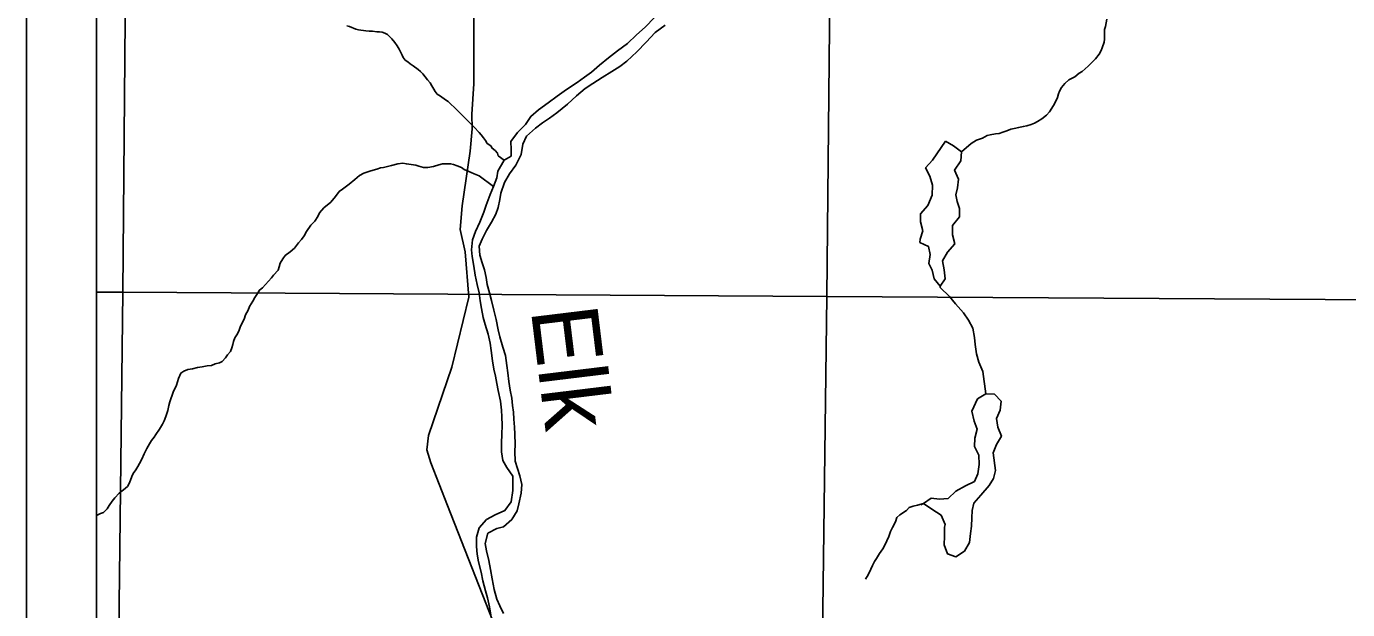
# Model space of a CAD drawing. Extents: x 0 to 34, y 0 to 22.
# Drawn here: x 2 to 3.881, y 17.696 to 18.526 of the extents above; entities that cross this region are included whole.
import ezdxf

# ---------------------------------------------------------------- set-up
doc = ezdxf.new("R2010")
doc.units = 0
for name, color, linetype in [('GM_X_Corporation', 7, 'Continuous'), ('GM_X_County_Road', 7, 'Continuous'), ('GM_X_Minor_River', 7, 'Continuous'), ('GM_X_Minor_River_Text', 7, 'Continuous'), ('SH_Data', 7, 'Continuous')]:
    doc.layers.add(name, color=color, linetype=linetype)

msp = doc.modelspace()

# ---------------------------------------------------------------- linework, layer by layer
at = {"layer": 'GM_X_Corporation'}
msp.add_lwpolyline([(8.2532, 20.898), (2.1, 20.898), (2.1, 14.098)], dxfattribs=at)
for points in [[(2.1, 19.147), (2.1, 18.1476), (2.1373, 18.1473), (2.1459, 19.1467)], [(2.1459, 19.1467), (3.1497, 19.1471), (3.1398, 18.1413), (2.1373, 18.1473)], [(4.1654, 19.1412), (4.1647, 18.1352), (3.1398, 18.1413), (3.1497, 19.1471)], [(2.1, 18.1476), (2.1, 17.1398), (2.1252, 17.1396), (2.1373, 18.1473)], [(3.1398, 18.1413), (3.1266, 17.137), (2.1252, 17.1396), (2.1373, 18.1473)], [(4.1647, 18.1352), (4.1603, 17.1368), (3.1266, 17.137), (3.1398, 18.1413)]]:
    msp.add_lwpolyline(points, close=True, dxfattribs=at)
at = {"layer": 'GM_X_County_Road'}
msp.add_lwpolyline([(2.674, 17.6542), (2.5993, 17.844), (2.5758, 17.9045), (2.5703, 17.9233), (2.5723, 17.9433), (2.6059, 18.0408), (2.6301, 18.1404), (2.6249, 18.205), (2.6178, 18.2367), (2.6206, 18.2704), (2.6317, 18.3484), (2.6345, 18.3799), (2.6342, 18.4007), (2.6368, 18.4443), (2.6367, 18.6447), (2.6405, 18.7534), (2.6409, 18.8215), (2.6479, 19.0479), (2.6495, 19.1471)], dxfattribs=at)
at = {"layer": 'GM_X_Minor_River'}
for points in [[(2.9071, 18.5517), (2.8808, 18.5249)], [(3.5384, 18.536), (3.5364, 18.5258), (3.5352, 18.5212), (3.5348, 18.5163), (3.5348, 18.5076), (3.5343, 18.5034), (3.5316, 18.4955), (3.5301, 18.4913), (3.5274, 18.4864), (3.5224, 18.4796), (3.5179, 18.4755), (3.5118, 18.4691), (3.5034, 18.4616), (3.4988, 18.4594), (3.4928, 18.4541), (3.4844, 18.45), (3.4783, 18.4444), (3.4737, 18.4387), (3.4711, 18.4338), (3.4695, 18.4297), (3.468, 18.4247), (3.4664, 18.4202), (3.4622, 18.413), (3.4565, 18.4044), (3.4523, 18.3995), (3.4458, 18.3942), (3.4397, 18.3905), (3.4352, 18.3883), (3.4306, 18.3864), (3.4246, 18.3842), (3.4193, 18.3831), (3.4128, 18.382), (3.4064, 18.3806), (3.4015, 18.3795), (3.3961, 18.3772), (3.3901, 18.3754), (3.3848, 18.3735), (3.3798, 18.3728), (3.3723, 18.3714), (3.3677, 18.3703), (3.3613, 18.3669), (3.3526, 18.364), (3.345, 18.3591), (3.3315, 18.3473)], [(2.4564, 18.5267), (2.4602, 18.5255), (2.4692, 18.5218), (2.473, 18.521), (2.4832, 18.5195), (2.4878, 18.519), (2.4927, 18.5189), (2.4991, 18.5183), (2.5025, 18.5179), (2.5067, 18.5174), (2.5105, 18.5161), (2.5142, 18.5141), (2.5205, 18.5079), (2.5246, 18.5028), (2.5279, 18.4982), (2.5308, 18.4936), (2.5348, 18.4851), (2.5366, 18.4817), (2.5391, 18.4778), (2.5429, 18.4754), (2.5466, 18.4727), (2.5507, 18.4699), (2.5578, 18.4644), (2.5612, 18.4616), (2.5645, 18.4581), (2.5711, 18.4496), (2.5748, 18.4453), (2.577, 18.4411), (2.5803, 18.4365), (2.5821, 18.433), (2.585, 18.4295), (2.5895, 18.4264), (2.5966, 18.4212), (2.6003, 18.4189), (2.6048, 18.4146), (2.6089, 18.4107), (2.613, 18.4071), (2.6178, 18.4024), (2.6244, 18.3958), (2.6274, 18.3923), (2.6326, 18.3869), (2.6374, 18.3822), (2.6444, 18.3748), (2.6474, 18.3713), (2.6507, 18.3674), (2.6536, 18.3635), (2.6562, 18.3593), (2.661, 18.3557), (2.6632, 18.3523), (2.6673, 18.3491), (2.6707, 18.3452), (2.6717, 18.3418), (2.6804, 18.3353)], [(2.8808, 18.5249), (2.8688, 18.5137), (2.8556, 18.5014), (2.8414, 18.491), (2.8287, 18.481), (2.8159, 18.4706), (2.8044, 18.4606), (2.7947, 18.4536), (2.784, 18.4458), (2.769, 18.4358), (2.7555, 18.4266), (2.7428, 18.4169), (2.7293, 18.4069), (2.7181, 18.3977), (2.7107, 18.3864), (2.6991, 18.3748), (2.6897, 18.3621), (2.6902, 18.3507), (2.69, 18.3412), (2.6804, 18.3353), (2.6714, 18.3199), (2.6697, 18.3104), (2.6649, 18.298), (2.6605, 18.2863), (2.6545, 18.2712), (2.6513, 18.2614), (2.6457, 18.247), (2.6393, 18.2338), (2.6353, 18.2218), (2.6339, 18.2077), (2.6348, 18.1982), (2.6372, 18.1845), (2.6388, 18.1719), (2.6416, 18.1585), (2.6444, 18.1467), (2.646, 18.1353), (2.6481, 18.1242), (2.6505, 18.1116), (2.6533, 18.1017), (2.6576, 18.0875), (2.6604, 18.0749), (2.6617, 18.0646), (2.6636, 18.0498), (2.6657, 18.0379), (2.6678, 18.028), (2.6698, 18.0173), (2.6715, 18.0074), (2.675, 17.9925), (2.6766, 17.9796), (2.6768, 17.9701), (2.6773, 17.9583), (2.6767, 17.945), (2.6764, 17.9328), (2.6766, 17.9203), (2.6782, 17.9077), (2.6841, 17.8977), (2.6925, 17.8854), (2.6927, 17.8747), (2.6925, 17.8652), (2.6903, 17.8489), (2.6813, 17.8369), (2.6672, 17.8304), (2.6553, 17.8241), (2.6448, 17.8122), (2.6407, 17.7989), (2.6408, 17.7853), (2.6417, 17.7746), (2.6438, 17.7635), (2.6473, 17.749), (2.6497, 17.7368), (2.6536, 17.7223), (2.6564, 17.7124), (2.6592, 17.6998), (2.6612, 17.6883)], [(2.6791, 17.6899), (2.674, 17.701), (2.6696, 17.7106), (2.6661, 17.7243), (2.663, 17.7392), (2.6606, 17.7526), (2.6582, 17.7655), (2.6551, 17.7793), (2.6534, 17.7896), (2.6571, 17.8043), (2.6698, 17.8109), (2.6793, 17.8134), (2.6909, 17.8238), (2.6988, 17.8362), (2.7012, 17.846), (2.7042, 17.8612), (2.7052, 17.8737), (2.7024, 17.8859), (2.6992, 17.8966), (2.696, 17.907), (2.6955, 17.9207), (2.6957, 17.9305), (2.6953, 17.9454), (2.6951, 17.9553), (2.6942, 17.9667), (2.6933, 17.9766), (2.6923, 17.9861), (2.691, 17.9964), (2.6886, 18.0078), (2.6869, 18.0204), (2.6853, 18.0326), (2.684, 18.0433), (2.682, 18.0574), (2.6781, 18.0692), (2.6742, 18.0838), (2.6717, 18.0937), (2.6686, 18.1086), (2.6655, 18.1219), (2.6624, 18.1357), (2.6592, 18.1464), (2.656, 18.1586), (2.6547, 18.1682), (2.6522, 18.1792), (2.649, 18.1892), (2.6458, 18.2003), (2.6446, 18.2132), (2.649, 18.223), (2.6549, 18.2354), (2.662, 18.2471), (2.6683, 18.2584), (2.6715, 18.2682), (2.674, 18.2792), (2.6757, 18.2886), (2.6806, 18.3034), (2.6876, 18.3161), (2.697, 18.3285), (2.7045, 18.3436), (2.7067, 18.3583), (2.7122, 18.3696), (2.725, 18.3808), (2.7346, 18.3886), (2.745, 18.3952), (2.755, 18.4026), (2.7704, 18.4149), (2.7832, 18.4272), (2.7955, 18.4372), (2.8067, 18.4446), (2.8198, 18.4531), (2.8336, 18.4615), (2.8451, 18.4689), (2.8551, 18.4763), (2.869, 18.4894), (2.8826, 18.5035), (2.8954, 18.517)], [(2.8954, 18.517), (2.9093, 18.5277)], [(3.272, 18.2184), (3.2844, 18.2125), (3.2868, 18.201), (3.2851, 18.1885), (3.2894, 18.1789), (3.2926, 18.1663), (3.3011, 18.1559), (3.3081, 18.1664), (3.3069, 18.1794), (3.3045, 18.1923), (3.3116, 18.2044), (3.3221, 18.2163), (3.3185, 18.2289), (3.3188, 18.2422), (3.3285, 18.2546), (3.3284, 18.2667), (3.3252, 18.2767), (3.3235, 18.2862), (3.3259, 18.2961), (3.327, 18.3086), (3.3215, 18.3212), (3.3305, 18.3344), (3.3315, 18.3473), (3.32, 18.3559), (3.3087, 18.3625)], [(3.3087, 18.3625), (3.29, 18.3355), (3.2802, 18.3243), (3.2861, 18.3124), (3.29, 18.2998), (3.2897, 18.2857), (3.2833, 18.2707), (3.2729, 18.2591), (3.273, 18.2477), (3.2762, 18.2347), (3.2725, 18.223), (3.272, 18.2184)], [(2.6649, 18.298), (2.6446, 18.3132), (2.6375, 18.3159), (2.6333, 18.3179), (2.6235, 18.3221), (2.6194, 18.3248), (2.6134, 18.3275), (2.6081, 18.3291), (2.6039, 18.3303), (2.5926, 18.33), (2.5873, 18.3289), (2.5797, 18.3263), (2.5714, 18.3249), (2.5653, 18.325), (2.5585, 18.3269), (2.5544, 18.3281), (2.5411, 18.3301), (2.5359, 18.3313), (2.5287, 18.3302), (2.5196, 18.328), (2.5086, 18.3251), (2.504, 18.3244), (2.4987, 18.3225), (2.4904, 18.3203), (2.4805, 18.317), (2.4741, 18.3137), (2.4676, 18.3077), (2.4596, 18.3013), (2.4501, 18.2942), (2.4452, 18.2908), (2.4402, 18.2836), (2.4333, 18.2754), (2.4235, 18.2675), (2.4174, 18.2603), (2.4151, 18.2554), (2.4105, 18.2486), (2.4051, 18.243), (2.3986, 18.234), (2.3956, 18.2279), (2.3917, 18.2223), (2.3872, 18.2178), (2.3818, 18.2102), (2.3757, 18.205), (2.3685, 18.1997), (2.3651, 18.1948), (2.3612, 18.1888), (2.3597, 18.1835), (2.3585, 18.179), (2.352, 18.1718), (2.349, 18.1677), (2.3448, 18.1632), (2.336, 18.1538), (2.3318, 18.1504), (2.3292, 18.1455), (2.3253, 18.1398), (2.3223, 18.1349), (2.3177, 18.127), (2.3158, 18.1217), (2.3119, 18.1153), (2.31, 18.1093), (2.305, 18.0991), (2.3031, 18.0934), (2.3004, 18.0881), (2.2969, 18.0825), (2.295, 18.0775), (2.2938, 18.073), (2.2923, 18.0685), (2.2907, 18.0632), (2.2865, 18.0583), (2.2835, 18.0541), (2.2789, 18.0489), (2.2747, 18.047), (2.2687, 18.0455), (2.2637, 18.0433), (2.2573, 18.0426), (2.2501, 18.0412), (2.2437, 18.0405), (2.2365, 18.0386), (2.2297, 18.0372), (2.224, 18.035), (2.2198, 18.0323), (2.2163, 18.0248), (2.2152, 18.0199), (2.2136, 18.015), (2.209, 18.0051), (2.2044, 17.9915), (2.2028, 17.9862), (2.2013, 17.979), (2.1985, 17.9704), (2.1962, 17.9643), (2.1939, 17.9594), (2.1897, 17.9526), (2.1844, 17.9451), (2.1817, 17.9409), (2.1779, 17.9364), (2.1752, 17.9315), (2.1714, 17.9251), (2.1675, 17.9172), (2.1641, 17.91), (2.161, 17.9036), (2.1587, 17.8994)], [(3.3011, 18.1559), (3.3011, 18.154), (3.3141, 18.1412), (3.323, 18.1311), (3.3341, 18.118), (3.3415, 18.1076), (3.3473, 18.0961), (3.3501, 18.0831), (3.351, 18.0732), (3.3526, 18.0599), (3.3562, 18.048), (3.3616, 18.0346), (3.3659, 18.0026)], [(3.307, 17.8129), (3.3072, 17.8004), (3.3069, 17.7878), (3.3116, 17.7748), (3.3232, 17.7708), (3.3355, 17.7789), (3.3426, 17.7913), (3.344, 17.8038), (3.3454, 17.8144), (3.346, 17.8262), (3.3466, 17.8365), (3.3491, 17.847), (3.3588, 17.8583), (3.3708, 17.8721), (3.3771, 17.8822), (3.3796, 17.8936), (3.3763, 17.9187), (3.3811, 17.9308), (3.3882, 17.9425), (3.3831, 17.9551), (3.3811, 17.9677), (3.3863, 17.9797), (3.388, 17.9923), (3.3784, 18.0023), (3.3659, 18.0026), (3.354, 17.9956)], [(3.354, 17.9956), (3.346, 17.9779), (3.3492, 17.9641), (3.3535, 17.9523), (3.3502, 17.9398), (3.3499, 17.928), (3.3561, 17.9153), (3.3566, 17.902), (3.3545, 17.8888), (3.3497, 17.8778), (3.337, 17.8716), (3.3232, 17.8643), (3.3124, 17.8538), (3.2999, 17.853), (3.2881, 17.8543), (3.2774, 17.8469), (3.289, 17.8387), (3.3024, 17.8301), (3.3079, 17.8167), (3.307, 17.8129)], [(2.1587, 17.8994), (2.1556, 17.8945), (2.1518, 17.8893), (2.1499, 17.8851), (2.1483, 17.8798), (2.1464, 17.8753), (2.1441, 17.8711), (2.138, 17.8659), (2.1319, 17.8614), (2.1258, 17.8546), (2.122, 17.8501), (2.1178, 17.8437), (2.1151, 17.8392), (2.1098, 17.8339), (2.1056, 17.8324), (2.1, 17.8298)], [(3.2737, 17.8449), (3.2774, 17.8469), (3.2686, 17.8444), (3.2625, 17.843), (3.2568, 17.8408), (3.253, 17.8366), (3.2435, 17.8306), (3.2393, 17.8269), (3.2374, 17.8205), (3.2332, 17.8125), (3.2305, 17.8069), (3.2278, 17.7997), (3.222, 17.7872), (3.2193, 17.7823), (3.2148, 17.7755), (3.2102, 17.7684), (3.2075, 17.7639), (3.2048, 17.7582), (3.2025, 17.7533), (3.1983, 17.745), (3.1948, 17.7389)]]:
    msp.add_lwpolyline(points, dxfattribs=at)
at = {"layer": 'SH_Data'}
for p, q in [((2, 20.998), (2, 13.998)), ((2.1, 20.898), (2.1, 14.098))]:
    msp.add_line(p, q, dxfattribs=at)

# ---------------------------------------------------------------- texts
at = {"layer": 'GM_X_Minor_River_Text'}
msp.add_text('Elk', height=0.09468, rotation=276.9443, dxfattribs=at).set_placement((2.7181, 18.1225))

doc.saveas('drawing.dxf')
